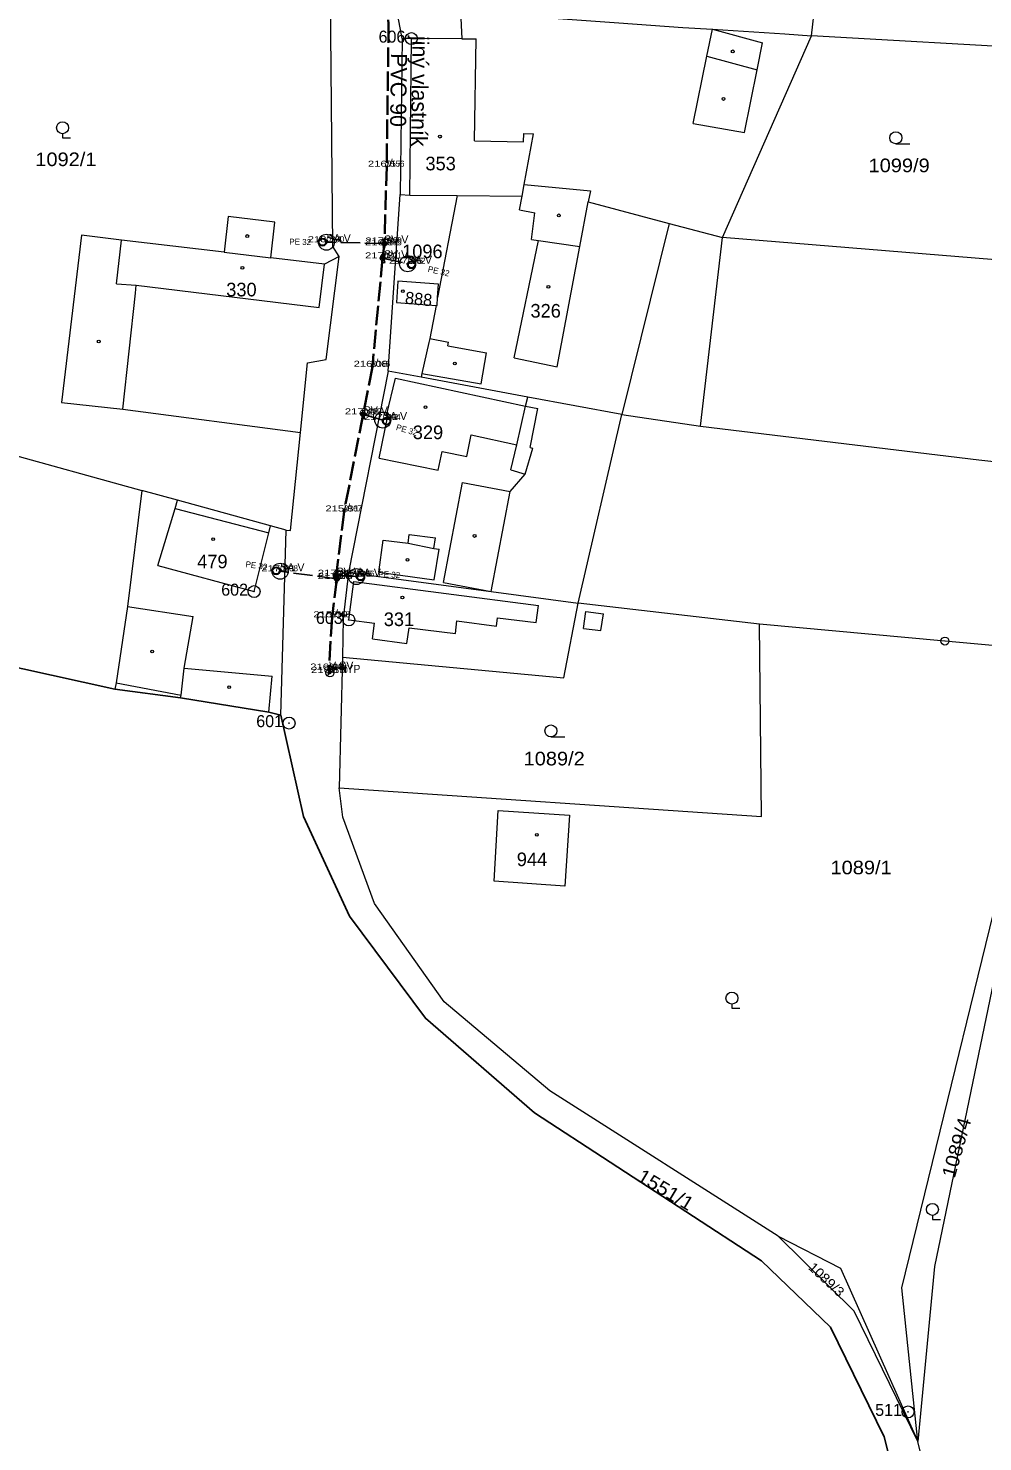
# Model space of a CAD drawing. Extents: x -686207 to -681951, y -1020493 to -1017811.
# Drawn here: x -684321.3 to -684202, y -1019774 to -1019597.4 of the extents above; entities that cross this region are included whole.
import ezdxf
from ezdxf.enums import TextEntityAlignment as Align

# ---------------------------------------------------------------- set-up
doc = ezdxf.new("R2010")
doc.units = 0
doc.header["$LTSCALE"] = 0.4
doc.header["$PDMODE"] = 32
doc.header["$PDSIZE"] = 0.2
doc.linetypes.add('DOTTED', pattern=[1.5, 0.3, -1.2])
doc.linetypes.add('LONG_DASHED', pattern=[7.5, 6, -1.5])
for name, color, linetype, lineweight in [('1', 7, 'Continuous', 13), ('10', 7, 'Continuous', 13), ('12', 7, 'Continuous', 13), ('24', 7, 'Continuous', 25), ('3', 7, 'Continuous', 13), ('35', 7, 'LONG_DASHED', 35), ('4', 7, 'Continuous', 13), ('5', 7, 'Continuous', 13), ('50', 7, 'LONG_DASHED', 25), ('51', 7, 'DOTTED', 25), ('8', 7, 'Continuous', 13)]:
    doc.layers.add(name, color=color, linetype=linetype, lineweight=lineweight)
for name, color, linetype in [('17', 7, 'Continuous'), ('19', 7, 'Continuous'), ('2', 7, 'Continuous')]:
    doc.layers.add(name, color=color, linetype=linetype)

msp = doc.modelspace()

# ---------------------------------------------------------------- linework, layer by layer
at = {"layer": '1'}
for p, q in [((-684274.59, -1019598.65), (-684274.81, -1019618.13)), ((-684234.54, -1019623.51), (-684223.41, -1019598.32)), ((-684276.32, -1019640.2), (-684274.81, -1019618.13)), ((-684267.71, -1019618.26), (-684270.15, -1019631)), ((-684241.18, -1019621.75), (-684247.12, -1019645.62)), ((-684270.34, -1019632), (-684271.13, -1019636.14)), ((-684363.38, -1019639.61), (-684307.12, -1019655.1)), ((-684276.32, -1019640.2), (-684281.27, -1019665.38)), ((-684252.56, -1019669.18), (-684247.12, -1019645.62)), ((-684289.75, -1019683.18), (-684289.09, -1019660.06)), ((-684282.05, -1019675.95), (-684282.45, -1019692.28)), ((-684252.49, -1019736.5), (-684258.05, -1019732.88)), ((-684206.62, -1019803.87), (-684214.34, -1019773.36)), ((-684202.75, -1019803.93), (-684210.11, -1019773.97))]:
    msp.add_line(p, q, dxfattribs=at)
for points in [[(-684282.45, -1019625.86), (-684283.23, -1019624.61), (-684283.59, -1019589.07), (-684288.88, -1019583.44), (-684330.26, -1019577.49)], [(-684274.59, -1019598.65), (-684276.64, -1019587.56), (-684276.9, -1019584.96), (-684276.02, -1019576.63)], [(-684194.13, -1019599.98), (-684223.41, -1019598.32), (-684222.47, -1019590.24)], [(-684267.3, -1019595.26), (-684267.13, -1019598.67), (-684273.42, -1019598.65), (-684274.59, -1019598.65)], [(-684267.3, -1019595.26), (-684247.49, -1019596.68), (-684239.49, -1019597.24), (-684235.8, -1019597.47), (-684226.76, -1019598.07), (-684223.41, -1019598.32)], [(-684274.81, -1019618.13), (-684273.62, -1019618.21), (-684267.71, -1019618.26)], [(-684267.71, -1019618.26), (-684259.58, -1019618.32), (-684259.31, -1019616.89), (-684251.05, -1019617.69), (-684251.31, -1019619.06), (-684241.18, -1019621.75), (-684234.54, -1019623.51)], [(-684282.45, -1019625.86), (-684284.3, -1019626.83), (-684291.01, -1019626.03), (-684290.48, -1019621.57), (-684296.31, -1019620.87), (-684296.84, -1019625.34), (-684309.65, -1019623.82), (-684314.65, -1019623.22), (-684317.14, -1019644.14), (-684309.49, -1019644.96), (-684287.3, -1019647.88)], [(-684194.09, -1019626.83), (-684198.38, -1019626.46), (-684234.54, -1019623.51)], [(-684287.3, -1019647.88), (-684286.42, -1019639.17), (-684284.09, -1019638.73), (-684282.45, -1019625.86)], [(-684270.15, -1019631), (-684270.02, -1019629.34), (-684275.11, -1019628.95), (-684275.3, -1019631.62), (-684270.34, -1019632)], [(-684270.34, -1019632), (-684270.22, -1019632.01), (-684270.15, -1019631)], [(-684271.13, -1019636.14), (-684271.24, -1019636.64), (-684272.11, -1019640.5), (-684272.21, -1019640.96), (-684276.32, -1019640.2)], [(-684247.12, -1019645.62), (-684258.87, -1019643.44), (-684272.21, -1019640.96)], [(-684247.12, -1019645.62), (-684237.29, -1019647.07), (-684202.48, -1019651.3), (-684146.93, -1019657.45)], [(-684289.09, -1019660.06), (-684288.53, -1019660.1), (-684287.3, -1019647.88)], [(-684307.12, -1019655.1), (-684308.91, -1019669.63), (-684310.33, -1019679.16), (-684310.5, -1019679.94)], [(-684289.09, -1019660.06), (-684291.04, -1019659.52), (-684302.64, -1019656.33), (-684307.12, -1019655.1)], [(-684281.27, -1019665.38), (-684281.93, -1019671.13), (-684282.05, -1019675.95)], [(-684281.27, -1019665.38), (-684263.43, -1019667.74), (-684252.56, -1019669.18)], [(-684282.45, -1019692.28), (-684229.64, -1019695.84), (-684229.91, -1019671.84), (-684252.56, -1019669.18)], [(-684282.05, -1019675.95), (-684254.36, -1019678.54), (-684252.56, -1019669.18)], [(-684289.75, -1019683.18), (-684291.23, -1019682.83), (-684302.3, -1019681.04), (-684310.5, -1019679.94), (-684353.33, -1019670.49)], [(-684185.62, -1019675.87), (-684206.72, -1019673.93), (-684229.91, -1019671.84)], [(-684258.05, -1019732.88), (-684271.66, -1019721.07), (-684281.16, -1019708.32), (-684286.92, -1019695.84), (-684289.75, -1019683.18)], [(-684227.58, -1019748.29), (-684256.12, -1019730.14), (-684269.33, -1019719.03), (-684278.05, -1019706.75), (-684281.99, -1019695.96), (-684282.45, -1019692.28)], [(-684210.11, -1019773.97), (-684212.11, -1019754.75), (-684196.83, -1019692.27), (-684186.78, -1019693.19)], [(-684186.78, -1019693.19), (-684195.88, -1019693.42), (-684208.04, -1019752.11), (-684210.11, -1019773.97)], [(-684214.34, -1019773.36), (-684221.01, -1019759.67), (-684229.65, -1019751.39), (-684252.49, -1019736.5)], [(-684227.58, -1019748.29), (-684219.8, -1019752.28), (-684210.11, -1019773.97)], [(-684210.11, -1019773.97), (-684218.08, -1019757.68), (-684227.58, -1019748.29)]]:
    msp.add_lwpolyline(points, dxfattribs=at)
msp.add_lwpolyline([(-684263.07, -1019703.95), (-684262.59, -1019695.1), (-684253.67, -1019695.7), (-684254.26, -1019704.58)], close=True, dxfattribs=at)
for p in [(-684276.51, -1019614.65), (-684284.04, -1019624.09), (-684276.87, -1019624.48), (-684276.84, -1019624.25), (-684276.87, -1019626.11), (-684273.89, -1019626.79), (-684278.3, -1019639.66), (-684279.4, -1019645.6), (-684277, -1019646.31), (-684281.83, -1019657.74), (-684289.83, -1019665.21), (-684282.79, -1019666.16), (-684282.78, -1019665.77), (-684280.28, -1019665.88), (-684283.34, -1019670.96), (-684283.72, -1019677.49), (-684283.61, -1019677.91)]:
    msp.add_point(p, dxfattribs=at)
at = {"layer": '10'}
for p, q in [((-684283.964, -1019678.264), (-684283.257, -1019677.557)), ((-684283.96, -1019677.11), (-684283.26, -1019677.11)), ((-684283.61, -1019677.41), (-684283.61, -1019677.11))]:
    msp.add_line(p, q, dxfattribs=at)
for points in [[(-684276.69, -1019624.75), (-684276.99, -1019623.75), (-684276.69, -1019623.75), (-684276.99, -1019624.75)], [(-684276.72, -1019626.61), (-684277.02, -1019625.61), (-684276.72, -1019625.61), (-684277.02, -1019626.61)], [(-684279.25, -1019646.1), (-684279.55, -1019645.1), (-684279.25, -1019645.1), (-684279.55, -1019646.1)], [(-684282.64, -1019666.66), (-684282.94, -1019665.66), (-684282.64, -1019665.66), (-684282.94, -1019666.66)], [(-684282.63, -1019666.27), (-684282.93, -1019665.27), (-684282.63, -1019665.27), (-684282.93, -1019666.27)], [(-684283.57, -1019677.99), (-684283.87, -1019676.99), (-684283.57, -1019676.99), (-684283.87, -1019677.99)]]:
    msp.add_lwpolyline(points, close=True, dxfattribs=at)
for centre, radius in [((-684284.04, -1019624.09), 1), ((-684273.89, -1019626.79), 1), ((-684277, -1019646.31), 1), ((-684289.83, -1019665.21), 1), ((-684280.28, -1019665.88), 1), ((-684283.609, -1019677.91), 0.5)]:
    msp.add_circle(centre, radius, dxfattribs=at)
at = {"layer": '12'}
for centre, radius in [((-684284.54, -1019624.079), 0.5), ((-684284.54, -1019624.079), 0.4), ((-684276.79, -1019624.251), 0.3), ((-684276.79, -1019624.251), 0.2), ((-684276.79, -1019624.251), 0.1), ((-684277.02, -1019626.076), 0.3), ((-684277.02, -1019626.076), 0.2), ((-684277.02, -1019626.076), 0.1), ((-684273.403, -1019626.901), 0.5), ((-684273.403, -1019626.901), 0.4), ((-684279.448, -1019645.586), 0.3), ((-684279.448, -1019645.586), 0.2), ((-684279.448, -1019645.586), 0.1), ((-684276.521, -1019646.452), 0.5), ((-684276.521, -1019646.452), 0.4), ((-684290.326, -1019665.143), 0.5), ((-684290.326, -1019665.143), 0.4), ((-684282.83, -1019665.768), 0.3), ((-684282.74, -1019666.167), 0.3), ((-684282.83, -1019665.768), 0.2), ((-684282.74, -1019666.167), 0.2), ((-684282.83, -1019665.768), 0.1), ((-684282.74, -1019666.167), 0.1), ((-684279.78, -1019665.902), 0.5), ((-684279.78, -1019665.902), 0.4)]:
    msp.add_circle(centre, radius, dxfattribs=at)
at = {"layer": '24'}
for points in [[(-684353.33, -1019670.49), (-684310.5, -1019679.94), (-684302.3, -1019681.04), (-684291.23, -1019682.83), (-684289.75, -1019683.18), (-684286.92, -1019695.84), (-684281.16, -1019708.32), (-684271.66, -1019721.07), (-684258.05, -1019732.88)], [(-684258.05, -1019732.88), (-684229.65, -1019751.39), (-684221.01, -1019759.67), (-684214.34, -1019773.36), (-684206.62, -1019803.87), (-684205.84, -1019810.38), (-684201.21, -1019842.45), (-684196.91, -1019872.26), (-684179.86, -1019990.28), (-684175.33, -1020021.63), (-684173.83, -1020032.04), (-684172.3, -1020042.64), (-684171.02, -1020051.5)]]:
    msp.add_lwpolyline(points, dxfattribs=at)
at = {"layer": '3'}
for p, q in [((-684212.863, -1019611.79), (-684211.113, -1019611.79)), ((-684255.983, -1019685.92), (-684254.233, -1019685.92))]:
    msp.add_line(p, q, dxfattribs=at)
for points in [[(-684317.03, -1019610.532), (-684317.03, -1019611.03), (-684316.029, -1019611.03)], [(-684233.35, -1019719.302), (-684233.35, -1019719.8), (-684232.349, -1019719.8)], [(-684208.3, -1019745.702), (-684208.3, -1019746.2), (-684207.299, -1019746.2)]]:
    msp.add_lwpolyline(points, dxfattribs=at)
for centre in [(-684317.0293, -1019609.7809), (-684212.8629, -1019611.0398), (-684255.9829, -1019685.1698), (-684233.3493, -1019718.5509), (-684208.2993, -1019744.9509)]:
    msp.add_circle(centre, 0.75, dxfattribs=at)
at = {"layer": '35'}
for p, q in [((-684276.79, -1019624.251), (-684277.02, -1019626.076)), ((-684282.83, -1019665.768), (-684282.74, -1019666.167))]:
    msp.add_line(p, q, dxfattribs=at)
for points in [[(-684276.95, -1019587.31), (-684276.27, -1019596.77), (-684276.51, -1019614.65), (-684276.79, -1019624.251)], [(-684277.02, -1019626.076), (-684278.3, -1019639.66), (-684279.448, -1019645.586)], [(-684279.448, -1019645.586), (-684281.83, -1019657.74), (-684282.83, -1019665.768)], [(-684282.74, -1019666.167), (-684283.34, -1019670.96), (-684283.72, -1019677.49), (-684283.61, -1019677.91)]]:
    msp.add_lwpolyline(points, dxfattribs=at)
at = {"layer": '4'}
for p, q in [((-684273.62, -1019618.21), (-684273.42, -1019598.65)), ((-684267.13, -1019598.67), (-684265.32, -1019598.67)), ((-684265.55, -1019611.43), (-684265.32, -1019598.67)), ((-684236.49, -1019600.83), (-684235.8, -1019597.47)), ((-684235.8, -1019597.47), (-684229.52, -1019599.17)), ((-684230.2, -1019602.53), (-684229.52, -1019599.17)), ((-684238.21, -1019609.25), (-684236.49, -1019600.83)), ((-684236.49, -1019600.83), (-684230.2, -1019602.53)), ((-684231.8, -1019610.4), (-684230.2, -1019602.53)), ((-684238.21, -1019609.25), (-684231.8, -1019610.4)), ((-684259.4, -1019611.54), (-684259.37, -1019610.51)), ((-684259.37, -1019610.51), (-684258.17, -1019610.53)), ((-684259.31, -1019616.89), (-684258.17, -1019610.53)), ((-684265.55, -1019611.43), (-684259.4, -1019611.54)), ((-684259.91, -1019620.06), (-684259.58, -1019618.32)), ((-684259.91, -1019620.06), (-684257.97, -1019620.43)), ((-684258.41, -1019623.75), (-684257.97, -1019620.43)), ((-684237.29, -1019647.07), (-684234.54, -1019623.51)), ((-684310.3, -1019629.28), (-684309.65, -1019623.82)), ((-684296.84, -1019625.34), (-684291.01, -1019626.03)), ((-684260.58, -1019638.55), (-684257.55, -1019623.86)), ((-684284.96, -1019632.25), (-684284.3, -1019626.83)), ((-684310.3, -1019629.28), (-684307.82, -1019629.45)), ((-684307.82, -1019629.45), (-684284.96, -1019632.25)), ((-684271.13, -1019636.14), (-684268.77, -1019636.57)), ((-684268.86, -1019637.06), (-684268.77, -1019636.57)), ((-684268.86, -1019637.06), (-684264.03, -1019637.91)), ((-684264.72, -1019641.77), (-684264.03, -1019637.91)), ((-684260.58, -1019638.55), (-684255.19, -1019639.66)), ((-684276.55, -1019645.73), (-684275.39, -1019641.09)), ((-684275.39, -1019641.09), (-684259.14, -1019644.56)), ((-684272.11, -1019640.5), (-684264.72, -1019641.77)), ((-684259.14, -1019644.56), (-684258.87, -1019643.44)), ((-684259.14, -1019644.56), (-684257.63, -1019644.88)), ((-684258.57, -1019649.74), (-684257.63, -1019644.88)), ((-684277.43, -1019651.07), (-684276.35, -1019645.78)), ((-684276.55, -1019645.73), (-684276.35, -1019645.78)), ((-684259.2, -1019653.08), (-684258.26, -1019649.83)), ((-684258.57, -1019649.74), (-684258.26, -1019649.83)), ((-684277.43, -1019651.07), (-684270.06, -1019652.57)), ((-684261.07, -1019655.26), (-684259.2, -1019653.08)), ((-684261.01, -1019652.55), (-684259.2, -1019653.08)), ((-684269.39, -1019666.63), (-684267.05, -1019654.12)), ((-684267.05, -1019654.12), (-684261.07, -1019655.26)), ((-684263.43, -1019667.74), (-684261.07, -1019655.26)), ((-684302.94, -1019657.35), (-684302.64, -1019656.33)), ((-684305.11, -1019664.51), (-684302.94, -1019657.35)), ((-684302.94, -1019657.35), (-684291.26, -1019660.41)), ((-684293.09, -1019667.76), (-684291.26, -1019660.41)), ((-684291.26, -1019660.41), (-684291.04, -1019659.52)), ((-684273.83, -1019661.71), (-684273.69, -1019660.6)), ((-684273.69, -1019660.6), (-684270.42, -1019661.04)), ((-684277.51, -1019665.32), (-684276.97, -1019661.32)), ((-684276.97, -1019661.32), (-684273.83, -1019661.71)), ((-684273.83, -1019661.71), (-684270.62, -1019662.37)), ((-684270.62, -1019662.37), (-684270.42, -1019661.04)), ((-684270.62, -1019662.37), (-684269.95, -1019662.47)), ((-684270.57, -1019666.27), (-684269.95, -1019662.47)), ((-684305.11, -1019664.51), (-684293.09, -1019667.76)), ((-684277.51, -1019665.32), (-684270.57, -1019666.27)), ((-684281.25, -1019671.29), (-684280.61, -1019666.48)), ((-684280.61, -1019666.48), (-684257.54, -1019669.5)), ((-684269.39, -1019666.63), (-684263.43, -1019667.74)), ((-684308.91, -1019669.63), (-684300.7, -1019670.85)), ((-684257.82, -1019671.6), (-684257.54, -1019669.5)), ((-684301.81, -1019677.34), (-684300.7, -1019670.85)), ((-684281.25, -1019671.29), (-684278.05, -1019671.7)), ((-684267.75, -1019671.39), (-684262.8, -1019672.08)), ((-684262.8, -1019672.08), (-684262.65, -1019671.01)), ((-684262.65, -1019671.01), (-684257.82, -1019671.6)), ((-684251.9, -1019672.38), (-684251.62, -1019670.22)), ((-684251.62, -1019670.22), (-684249.41, -1019670.51)), ((-684249.73, -1019672.61), (-684249.41, -1019670.51)), ((-684278.27, -1019673.64), (-684278.05, -1019671.7)), ((-684273.98, -1019674.25), (-684273.7, -1019672.26)), ((-684251.9, -1019672.38), (-684249.73, -1019672.61)), ((-684278.27, -1019673.64), (-684273.98, -1019674.25)), ((-684302.22, -1019680.7), (-684301.81, -1019677.34)), ((-684301.81, -1019677.34), (-684290.83, -1019678.34)), ((-684291.23, -1019682.83), (-684290.83, -1019678.34)), ((-684310.33, -1019679.16), (-684302.22, -1019680.7)), ((-684302.3, -1019681.04), (-684302.22, -1019680.7))]:
    msp.add_line(p, q, dxfattribs=at)
for points in [[(-684255.19, -1019639.66), (-684252.36, -1019624.62), (-684251.31, -1019619.06)], [(-684258.41, -1019623.75), (-684257.55, -1019623.86), (-684252.36, -1019624.62)], [(-684309.49, -1019644.96), (-684307.93, -1019630.45), (-684307.82, -1019629.45)], [(-684261.01, -1019652.55), (-684260.22, -1019649.42), (-684259.14, -1019644.56)], [(-684266.5, -1019650.89), (-684265.94, -1019648.16), (-684260.22, -1019649.42)], [(-684270.06, -1019652.57), (-684269.59, -1019650.26), (-684266.5, -1019650.89)], [(-684273.7, -1019672.26), (-684267.92, -1019672.99), (-684267.75, -1019671.39)]]:
    msp.add_lwpolyline(points, dxfattribs=at)
at = {"layer": '5'}
for centre in [(-684233.2568, -1019600.2392), (-684234.3968, -1019606.1892), (-684269.8468, -1019610.8992), (-684254.9968, -1019620.7392), (-684293.9368, -1019623.3192), (-684294.5468, -1019627.2892), (-684274.4968, -1019630.2092), (-684256.2968, -1019629.6592), (-684312.5068, -1019636.4892), (-684267.9968, -1019639.2592), (-684271.6668, -1019644.7092), (-684265.5168, -1019660.7992), (-684298.1968, -1019661.2092), (-684273.8968, -1019663.7792), (-684274.5468, -1019668.4992), (-684305.8268, -1019675.2392), (-684296.1968, -1019679.6992), (-684257.7468, -1019698.1392)]:
    msp.add_circle(centre, 0.175, dxfattribs=at)
at = {"layer": '50'}
for p, q in [((-684276.84, -1019624.25), (-684284.04, -1019624.09)), ((-684276.79, -1019624.251), (-684276.84, -1019624.25)), ((-684279.448, -1019645.586), (-684279.4, -1019645.6)), ((-684279.4, -1019645.6), (-684277, -1019646.31)), ((-684282.79, -1019666.16), (-684289.83, -1019665.21)), ((-684282.83, -1019665.768), (-684282.78, -1019665.77)), ((-684282.74, -1019666.167), (-684282.79, -1019666.16)), ((-684282.78, -1019665.77), (-684280.28, -1019665.88))]:
    msp.add_line(p, q, dxfattribs=at)
msp.add_lwpolyline([(-684277.02, -1019626.076), (-684276.87, -1019626.11), (-684273.89, -1019626.79)], dxfattribs=at)
at = {"layer": '51'}
for p, q in [((-684284.04, -1019624.09), (-684284.54, -1019624.079)), ((-684273.89, -1019626.79), (-684273.403, -1019626.901)), ((-684277, -1019646.31), (-684276.521, -1019646.452)), ((-684289.83, -1019665.21), (-684290.326, -1019665.143)), ((-684280.28, -1019665.88), (-684279.78, -1019665.902))]:
    msp.add_line(p, q, dxfattribs=at)
at = {"layer": '8'}
for centre, radius in [((-684273.42, -1019598.6498), 0.75), ((-684273.42, -1019598.6498), 0.03), ((-684293.09, -1019667.7598), 0.75), ((-684293.09, -1019667.7598), 0.03), ((-684281.25, -1019671.2898), 0.75), ((-684281.25, -1019671.2898), 0.03), ((-684206.72, -1019673.9299), 0.5), ((-684206.72, -1019673.9299), 0.0303), ((-684288.71, -1019684.1898), 0.75), ((-684288.71, -1019684.1898), 0.03), ((-684211.34, -1019770.2598), 0.75), ((-684211.34, -1019770.2598), 0.03)]:
    msp.add_circle(centre, radius, dxfattribs=at)

# ---------------------------------------------------------------- texts
at = {"layer": '17'}
for s, p in [('jiný vlastník', (-684273.3829, -1019605.2141)), ('PVC 90', (-684276.0254, -1019605.0616))]:
    msp.add_text(s, height=2, rotation=269.231, dxfattribs=at).set_placement(p, align=Align.CENTER)
at = {"layer": '19'}
for rotation, p in [(358.727, (-684287.3298, -1019624.4212)), (347.146, (-684270.0909, -1019628.0859)), (343.52, (-684274.0909, -1019647.9218)), (352.315, (-684292.8441, -1019664.8671)), (357.481, (-684276.201, -1019665.9948))]:
    msp.add_text('PE 32', height=0.75, rotation=rotation, dxfattribs=at).set_placement(p, align=Align.CENTER)
at = {"layer": '2', "width": 1.1}
for s, p in [('1092/1', (-684320.435, -1019614.58)), ('1099/9', (-684216.275, -1019615.34)), ('1089/2', (-684259.395, -1019689.47)), ('1089/1', (-684221.03, -1019703.08))]:
    msp.add_text(s, height=1.7, dxfattribs=at).set_placement(p)
at = {"layer": '2'}
for s, height, p in [('0156', 0.75, (-684276.51, -1019614.65)), ('353', 1.7, (-684271.664, -1019615.11)), ('0200', 0.75, (-684284.04, -1019624.09)), ('0165', 0.75, (-684276.87, -1019624.48)), ('0199', 0.75, (-684276.84, -1019624.25)), ('0201', 0.75, (-684276.87, -1019626.11)), ('1096', 1.7, (-684274.577, -1019626.09)), ('0202', 0.75, (-684273.89, -1019626.79)), ('330', 1.7, (-684296.564, -1019630.86)), ('326', 1.7, (-684258.534, -1019633.51)), ('0166', 0.75, (-684278.3, -1019639.66)), ('0203', 0.75, (-684279.4, -1019645.6)), ('0204', 0.75, (-684277, -1019646.31)), ('329', 1.7, (-684273.244, -1019648.7)), ('0167', 0.75, (-684281.83, -1019657.74)), ('479', 1.7, (-684300.194, -1019664.84)), ('0208', 0.75, (-684289.83, -1019665.21)), ('0207', 0.75, (-684282.79, -1019666.16)), ('0205', 0.75, (-684282.78, -1019665.77)), ('0206', 0.75, (-684280.28, -1019665.88)), ('0168', 0.75, (-684283.34, -1019670.96)), ('331', 1.7, (-684276.874, -1019672.059)), ('0169', 0.75, (-684283.72, -1019677.49)), ('0170', 0.75, (-684283.61, -1019677.91)), ('944', 1.7, (-684260.244, -1019702.059))]:
    msp.add_text(s, height=height, dxfattribs=at).set_placement(p)
msp.add_text('888', height=1.518, rotation=354, dxfattribs=at).set_placement((-684274.273, -1019631.76))
at = {"layer": '2', "width": 1.1}
for s, height, rotation, p in [('1089/4', 1.7, 74, (-684205.512, -1019741.144)), ('1551/1', 1.7, 329, (-684245.351, -1019741.256)), ('1089/3', 1.19, 317, (-684223.895, -1019752.325))]:
    msp.add_text(s, height=height, rotation=rotation, dxfattribs=at).set_placement(p)
at = {"layer": '3', "width": 1.4}
for s, p in [('216 57 ', (-684276.51, -1019614.65)), ('218 14 ', (-684284.04, -1019624.09)), ('216 37 ', (-684276.87, -1019624.48)), ('217 87 ', (-684276.84, -1019624.25)), ('217 81 ', (-684276.87, -1019626.11)), ('217 95 ', (-684273.89, -1019626.79)), ('216 08 ', (-684278.3, -1019639.66)), ('217 48 ', (-684279.4, -1019645.6)), ('217 82 ', (-684277, -1019646.31)), ('215 81 ', (-684281.83, -1019657.74)), ('217 21 ', (-684289.83, -1019665.21)), ('217 03 ', (-684282.79, -1019666.16)), ('217 22 ', (-684282.78, -1019665.77)), ('217 25 ', (-684280.28, -1019665.88)), ('215 50 ', (-684283.34, -1019670.96)), ('216 98 ', (-684283.72, -1019677.49)), ('216 85 ', (-684283.61, -1019677.91))]:
    msp.add_text(s, height=0.75, dxfattribs=at).set_placement(p, align=Align.CENTER)
at = {"layer": '4'}
for s, width, p in [('V', 0.85, (-684276.51, -1019614.65)), ('V', 0.85, (-684276.87, -1019624.48)), ('V', 0.85, (-684278.3, -1019639.66)), ('V', 0.85, (-684281.83, -1019657.74)), ('V', 0.85, (-684283.34, -1019670.96)), ('V HYP', 0.95, (-684283.61, -1019677.91))]:
    msp.add_text(s, height=1, dxfattribs=dict(at, width=width)).set_placement(p)
for s, p in [('SA V', (-684284.04, -1019624.09)), ('SV V', (-684276.84, -1019624.25)), ('SV V', (-684276.87, -1019626.11)), ('SA V', (-684273.89, -1019626.79)), ('SV V', (-684279.4, -1019645.6)), ('SA V', (-684277, -1019646.31)), ('SA V', (-684289.83, -1019665.21)), ('SV V', (-684282.79, -1019666.16)), ('SV V', (-684282.78, -1019665.77)), ('SA V', (-684280.28, -1019665.88)), ('V SV', (-684283.72, -1019677.49))]:
    msp.add_text(s, height=1, dxfattribs=at).set_placement(p)
at = {"layer": '8'}
for s, p in [('606', (-684277.523, -1019599.15)), ('602', (-684297.193, -1019668.26)), ('603', (-684285.353, -1019671.79)), ('601', (-684292.813, -1019684.69)), ('511', (-684215.443, -1019770.76))]:
    msp.add_text(s, height=1.5, dxfattribs=at).set_placement(p)

doc.saveas('drawing.dxf')
